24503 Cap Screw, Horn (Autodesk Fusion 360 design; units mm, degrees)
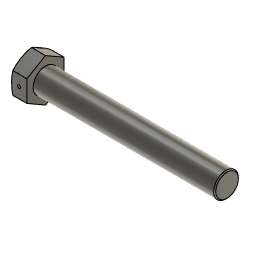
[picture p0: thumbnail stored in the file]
sketch "Main Profile" plane through (0, 0, 0) normal (0, 1, 0) x axis (1, 0, 0)
  line L1 (75.8031, 0) -> (0, 0)
  line L2 (75.8031, -4.7625) -> (75.8031, 0)
  line L3 (5.9531, -4.7625) -> (75.8031, -4.7625)
  line L4 (5.9531, -7.1437) -> (5.9531, -4.7625)
  line L5 (0, -7.1437) -> (5.9531, -7.1437)
  line L6 (0, 0) -> (0, -7.1437)
  point P1 (0, 0)
  point P2 (0, 0)
  point P8 (0, 0)
  point P7 (0, -7.1437)
  point P6 (5.9531, -7.1437)
  point P3 (75.8031, 0)
  point P4 (75.8031, -4.7625)
  coincident P1 P2
  horizontal L1
  perpendicular L1 L2
  perpendicular L2 L3
  perpendicular L3 L4
  perpendicular L4 L5
  coincident P1 P8
  perpendicular L1 L6
  dimension "d1" distance P7 P8 = 7.1437 (= "( 9 / 32 ) * 1 in")
  dimension "d2" distance P6 P7 = 5.9531 (= "( 15 / 64 ) * 1 in")
  dimension "d3" distance P3 P4 = 4.7625 (= "( 3 / 16 ) * 1 in")
  dimension "d4" distance L2 P6 = 69.85 (= "2 3/4")
revolve "Revolve1" sketch "Main Profile" AlongAngle 360 bodies "24503 Cap Screw, Horn"
chamfer "Chamfer1" distance 0.3969 (= "( 1 / 64 ) * 1 in")
sketch "Hex Profile" plane through (0, 0, 0) normal (-1, 0, 0) x axis (0, -1, 0)
  line L1 (-7.1437, 4.1244) -> (0, 8.2489)
  line L2 (-7.1437, -4.1244) -> (-7.1437, 4.1244)
  line L3 (0, -8.2489) -> (-7.1437, -4.1244)
  line L4 (7.1437, -4.1244) -> (0, -8.2489)
  line L5 (7.1438, 4.1244) -> (7.1437, -4.1244)
  line L6 (0, 8.2489) -> (7.1438, 4.1244)
  line L7 (0, 8.2489) -> (0, 0)
  circle C1 centre (0, 0) radius 7.1437
  point P1 (0, 0)
  point P9 (0, 0)
  point P10 (0, 0)
  coincident P1 P9
  coincident P1 P10
  vertical L7
  dimension "d7" distance L2 L5 = 14.2875 (= "( 9 / 16 ) * 1 in")
extrude "Extrude1" add sketch "Hex Profile" profile of C1 L1 L2 L3 L4 L5 L6 against normal blind 5.9531 (magnitude of "( -15 / 64 ) * 1 in")
sketch "Hex Cut Profile" plane through (0, 0, 0) normal (0, 1, 0) x axis (1, 0, 0)
  line L1 (0, -4.1244) -> (0, -8.2489)
  line L2 (5.9531, -4.1244) -> (0, -4.1244)
  line L3 (5.9531, -8.2489) -> (5.9531, -4.1244)
  line L4 (0, -8.2489) -> (5.9531, -8.2489)
  line L5 (0.5552, -8.2489) -> (0, -7.0583)
  point P6 (0, -7.0583)
  point P7 (0.5552, -8.2489)
  coincident L1 P6
  coincident L4 P7
  dimension "d10" angle L1 L5 = 25
  dimension "d11" distance P6 P7 = 1.1906 (= "( 3 / 64 ) * 1 in")
revolve "Revolve2" sketch "Hex Cut Profile" AlongAngle 360
sketch "Wire Seal Hole Profile" plane through (0, -7.1437, 0) normal (0, -1, 0) x axis (1, 0, 0)
  curve K1 (0.5552, -4.1244) -> (0.5552, 4.1244)
  line L1 (5.9531, -4.1244) -> (0.5552, -4.1244)
  line L2 (5.9531, 4.1244) -> (5.9531, -4.1244)
  line L3 (0.5552, 4.1244) -> (5.9531, 4.1244)
  line L4 (5.9531, 0) -> (0, 0)
  circle C1 centre (2.9766, 0) radius 0.5953
  point P1 (0, 0)
  point P6 (0, 0)
  point P7 (5.9531, 0)
  point P8 (2.9766, 0)
  coincident P1 P6
  midpoint L2 P7
  midpoint L4 P8
  dimension "d13" diameter C1 = 1.1906 (= "( 3 / 64 ) * 1 in")
extrude "Extrude2" cut sketch "Wire Seal Hole Profile" profile of C1 against normal blind 14.3002
named bodies: "24503 Cap Screw, Horn"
